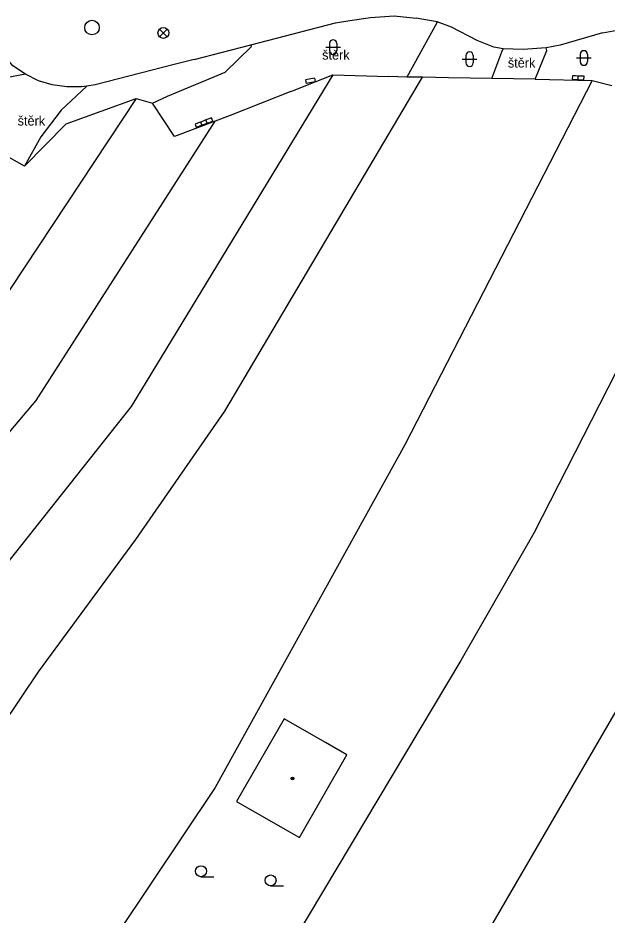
# Model space of a CAD drawing. Extents: x -595546 to -593986, y -1160845 to -1159202.
# Drawn here: x -594789.1 to -594748.8, y -1160341.6 to -1160280.2 of the extents above; entities that cross this region are included whole.
import ezdxf

# ---------------------------------------------------------------- set-up
doc = ezdxf.new("R2010")
doc.units = 0
for name, color, linetype in [('DOP - budovy nerozlisene - VP', 7, 'Continuous'), ('DOP - rozhrani ploch obecne', 7, 'Continuous'), ('Level 17', 7, 'Continuous'), ('Level 27', 7, 'Continuous'), ('Level 36', 7, 'Continuous'), ('Level 39', 7, 'Continuous'), ('plynovod - povrch.  znaky - PRIS skut. velikost', 7, 'Continuous'), ('silnoproud - povrch.  znaky a  RIS  skut. velikost', 7, 'Continuous'), ('TM - chodniky - VP', 7, 'Continuous'), ('TM - komunikace - VP', 7, 'Continuous'), ('TM - letecke snimky - pomocna linie', 7, 'Continuous'), ('TM - plot drateny_ kovovy - VP', 7, 'Continuous'), ('TM - popis povrchu', 7, 'Continuous'), ('TM - vjezd na pozemek', 7, 'Continuous')]:
    doc.layers.add(name, color=color, linetype=linetype)

msp = doc.modelspace()

# ---------------------------------------------------------------- linework, layer by layer
at = {"layer": 'DOP - budovy nerozlisene - VP'}
for points in [[(-594770.89, -1160328.2), (-594774.15, -1160333.86)], [(-594768.08, -1160329.83), (-594770.89, -1160328.2)], [(-594766.6, -1160330.68), (-594768.08, -1160329.83)], [(-594769.86, -1160336.33), (-594766.6, -1160330.68)], [(-594774.15, -1160333.86), (-594771.33, -1160335.49)], [(-594771.33, -1160335.49), (-594769.86, -1160336.33)]]:
    msp.add_lwpolyline(points, dxfattribs=at)
at = {"layer": 'DOP - rozhrani ploch obecne'}
for points in [[(-594767.57, -1160284.13), (-594781.38, -1160306.84)], [(-594774.95, -1160307.16), (-594761.43, -1160284.3)], [(-594749.82, -1160284.52), (-594762.65, -1160309.46)], [(-594781.02, -1160285.75), (-594794.42, -1160305.96)], [(-594787.86, -1160306.42), (-594775.62, -1160287.3)], [(-594742.02, -1160292.39), (-594753.82, -1160315.5)], [(-594798.61, -1160319.14), (-594787.86, -1160306.42)], [(-594781.38, -1160306.84), (-594818.13, -1160353.2)], [(-594781.06, -1160315.93), (-594774.95, -1160307.16)], [(-594762.65, -1160309.46), (-594775.62, -1160332.92)], [(-594753.82, -1160315.5), (-594758.81, -1160324.21)], [(-594787.72, -1160324.99), (-594781.06, -1160315.93)], [(-594757.99, -1160344.57), (-594745.81, -1160323.6)], [(-594758.81, -1160324.21), (-594774.86, -1160351.12)], [(-594793.96, -1160334.28), (-594787.72, -1160324.99)], [(-594775.62, -1160332.92), (-594788.94, -1160352.83)]]:
    msp.add_lwpolyline(points, dxfattribs=at)
at = {"layer": 'Level 17'}
for p, q in [((-594779.425, -1160281.525), (-594778.895, -1160280.995)), ((-594779.425, -1160280.995), (-594778.895, -1160281.525))]:
    msp.add_line(p, q, dxfattribs=at)
msp.add_circle((-594779.16, -1160281.26), 0.375, dxfattribs=at)
at = {"layer": 'Level 27'}
msp.add_circle((-594784.05, -1160280.89), 0.5, dxfattribs=at)
at = {"layer": 'Level 36'}
for p, q in [((-594767.796, -1160281.976), (-594767.796, -1160282.476)), ((-594767.296, -1160281.976), (-594767.296, -1160282.476)), ((-594768.046, -1160282.226), (-594767.046, -1160282.226)), ((-594758.706, -1160283.056), (-594757.706, -1160283.056)), ((-594758.456, -1160282.806), (-594758.456, -1160283.306)), ((-594757.956, -1160282.806), (-594757.956, -1160283.306)), ((-594750.886, -1160282.976), (-594749.886, -1160282.976)), ((-594750.636, -1160282.726), (-594750.636, -1160283.226)), ((-594750.136, -1160282.726), (-594750.136, -1160283.226)), ((-594776.59, -1160339.015), (-594775.715, -1160339.015)), ((-594771.83, -1160339.645), (-594770.955, -1160339.645))]:
    msp.add_line(p, q, dxfattribs=at)
for centre in [(-594776.59, -1160338.64), (-594771.83, -1160339.27)]:
    msp.add_circle(centre, 0.375, dxfattribs=at)
for centre, start, end in [((-594767.546, -1160281.976), 0, 180), ((-594767.546, -1160282.476), 180, 0), ((-594758.206, -1160282.806), 0, 180), ((-594750.386, -1160282.726), 0, 180), ((-594758.206, -1160283.306), 180, 0), ((-594750.386, -1160283.226), 180, 0)]:
    msp.add_arc(centre, 0.25, start, end, dxfattribs=at)
at = {"layer": 'Level 39'}
for radius in [0.09, 0.09, 0.0398, 0.0398]:
    msp.add_circle((-594770.33, -1160332.3), radius, dxfattribs=at)
at = {"layer": 'plynovod - povrch.  znaky - PRIS skut. velikost'}
for points in [[(-594768.83, -1160284.36), (-594769.44, -1160284.48)], [(-594769.44, -1160284.48), (-594769.39, -1160284.73)], [(-594768.83, -1160284.36), (-594768.78, -1160284.61)], [(-594768.78, -1160284.61), (-594769.39, -1160284.73)]]:
    msp.add_lwpolyline(points, dxfattribs=at)
at = {"layer": 'silnoproud - povrch.  znaky a  RIS  skut. velikost'}
for points in [[(-594751.17, -1160284.19), (-594751.18, -1160284.43)], [(-594751.18, -1160284.43), (-594750.78, -1160284.45)], [(-594750.97, -1160284.2), (-594751.17, -1160284.19)], [(-594750.77, -1160284.21), (-594750.97, -1160284.2)], [(-594750.78, -1160284.45), (-594750.77, -1160284.21)], [(-594750.78, -1160284.45), (-594750.38, -1160284.47)], [(-594750.57, -1160284.22), (-594750.77, -1160284.21)], [(-594750.37, -1160284.23), (-594750.57, -1160284.22)], [(-594750.38, -1160284.47), (-594750.37, -1160284.23)], [(-594776.82, -1160287.43), (-594777, -1160287.5)], [(-594777, -1160287.5), (-594776.91, -1160287.72)], [(-594776.91, -1160287.72), (-594776.54, -1160287.58)], [(-594776.63, -1160287.36), (-594776.82, -1160287.43)], [(-594776.44, -1160287.29), (-594776.63, -1160287.36)], [(-594776.63, -1160287.36), (-594776.54, -1160287.58)], [(-594776.54, -1160287.58), (-594776.16, -1160287.44)], [(-594776.25, -1160287.22), (-594776.44, -1160287.29)], [(-594776.06, -1160287.15), (-594776.25, -1160287.22)], [(-594776.16, -1160287.44), (-594776.25, -1160287.22)], [(-594776.16, -1160287.44), (-594775.79, -1160287.3)], [(-594775.88, -1160287.08), (-594776.06, -1160287.15)], [(-594775.79, -1160287.3), (-594775.88, -1160287.08)]]:
    msp.add_lwpolyline(points, dxfattribs=at)
at = {"layer": 'TM - chodniky - VP'}
for points in [[(-594760.44, -1160280.58), (-594762.5, -1160284.28)], [(-594773.14, -1160282.2), (-594773.17, -1160282.07)], [(-594779.9, -1160286.07), (-594778.89, -1160285.59), (-594774.93, -1160283.94), (-594773.14, -1160282.2)], [(-594756.69, -1160284.38), (-594755.99, -1160282.55)], [(-594755.99, -1160282.55), (-594755.92, -1160282.36)], [(-594753.72, -1160284.42), (-594752.93, -1160282.46)], [(-594752.93, -1160282.46), (-594752.96, -1160282.27)], [(-594788.6, -1160284.09), (-594792.72, -1160284.87)]]:
    msp.add_lwpolyline(points, dxfattribs=at)
at = {"layer": 'TM - komunikace - VP'}
for points in [[(-594773.17, -1160282.07), (-594767.38, -1160280.57), (-594766.4, -1160280.42), (-594764.98, -1160280.21), (-594763.38, -1160280.09), (-594761.87, -1160280.26)], [(-594760.42, -1160280.5), (-594761.87, -1160280.26)], [(-594760.42, -1160280.5), (-594760.44, -1160280.58)], [(-594755.92, -1160282.36), (-594756.56, -1160282.23), (-594757.68, -1160281.79), (-594759.44, -1160280.86), (-594760.42, -1160280.5)], [(-594749.12, -1160281.26), (-594752, -1160282.09), (-594752.96, -1160282.27)], [(-594749.12, -1160281.26), (-594748.1, -1160281.08), (-594747.1, -1160281.08)], [(-594788.6, -1160284.09), (-594789.46, -1160283.52), (-594790.24, -1160282.56), (-594790.72, -1160281.83)], [(-594777.06, -1160283.07), (-594773.17, -1160282.07)], [(-594754.53, -1160282.39), (-594755.92, -1160282.36)], [(-594752.96, -1160282.27), (-594754.53, -1160282.39)], [(-594777.06, -1160283.07), (-594778.43, -1160283.42), (-594783.84, -1160284.82)], [(-594784.77, -1160284.95), (-594785.77, -1160284.95), (-594786.77, -1160284.82), (-594787.71, -1160284.54), (-594788.6, -1160284.09)], [(-594784.4, -1160284.9), (-594784.77, -1160284.95)], [(-594783.84, -1160284.82), (-594784.4, -1160284.9)]]:
    msp.add_lwpolyline(points, dxfattribs=at)
at = {"layer": 'TM - letecke snimky - pomocna linie'}
msp.add_lwpolyline([(-594784.4, -1160284.9), (-594786.16, -1160286.54), (-594787.56, -1160288.37), (-594788.66, -1160290.39)], dxfattribs=at)
at = {"layer": 'TM - plot drateny_ kovovy - VP'}
for points in [[(-594768.78, -1160284.61), (-594767.57, -1160284.13)], [(-594767.57, -1160284.13), (-594763.74, -1160284.25)], [(-594761.43, -1160284.3), (-594762.5, -1160284.28)], [(-594759.64, -1160284.33), (-594761.43, -1160284.3)], [(-594756.69, -1160284.38), (-594759.64, -1160284.33)], [(-594753.72, -1160284.42), (-594749.82, -1160284.52)], [(-594749.82, -1160284.52), (-594748.48, -1160284.85)], [(-594770.45, -1160285.26), (-594768.78, -1160284.61)], [(-594788.66, -1160290.39), (-594785.81, -1160287.48), (-594781.02, -1160285.75)], [(-594781.02, -1160285.75), (-594779.9, -1160286.07)], [(-594774.59, -1160286.91), (-594775.62, -1160287.3)], [(-594775.62, -1160287.3), (-594778.41, -1160288.35)]]:
    msp.add_lwpolyline(points, dxfattribs=at)
at = {"layer": 'TM - vjezd na pozemek'}
for points in [[(-594762.5, -1160284.28), (-594763.74, -1160284.25)], [(-594753.72, -1160284.42), (-594756.69, -1160284.38)], [(-594770.45, -1160285.26), (-594774.59, -1160286.91)], [(-594778.41, -1160288.35), (-594779.9, -1160286.07)], [(-594788.66, -1160290.39), (-594790.9, -1160289.12)]]:
    msp.add_lwpolyline(points, dxfattribs=at)

# ---------------------------------------------------------------- texts
at = {"layer": 'TM - popis povrchu'}
for p in [(-594768.3, -1160283.09), (-594755.59, -1160283.63), (-594789.14, -1160287.6)]:
    msp.add_text('štěrk', height=0.65, dxfattribs=at).set_placement(p)

doc.saveas('drawing.dxf')
